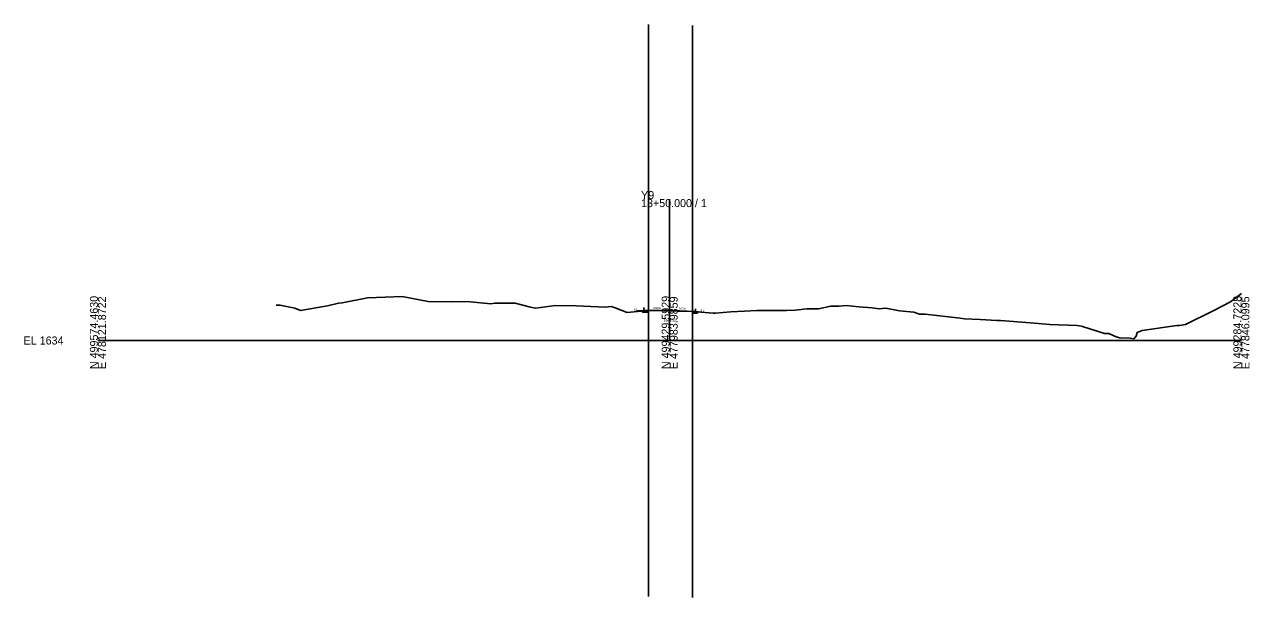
# Model space of a CAD drawing. Extents: x -26 to 403, y -99 to 4540.
# Drawn here: x -25.7 to 402.8, y 3410.1 to 3610.5 of the extents above; entities that cross this region are included whole.
import ezdxf

# ---------------------------------------------------------------- set-up
doc = ezdxf.new("R2010")
doc.units = 0
for name, color, linetype in [('Exist Cross Section Cell', 7, 'Continuous'), ('Exist XS Center Line Elevation Label', 7, 'Continuous'), ('Exist XS Ground Line', 7, 'Continuous'), ('Prop XS Ditch Slope Text', 7, 'Continuous'), ('Prop XS Dump Level', 7, 'Continuous'), ('Prop XS Earthwork Shape', 7, 'Continuous'), ('Prop XS EOT Tick Mark', 7, 'Continuous'), ('Prop XS Finish Grade', 7, 'Continuous'), ('Prop XS Finish Grade Earthwork', 7, 'Continuous'), ('Prop XS Finish Grade Pavement', 7, 'Continuous'), ('Prop XS Pvmt Edge Slope', 7, 'Continuous'), ('Prop XS SE Text', 7, 'Continuous'), ('Prop XS Shoulder Borrow Shape', 7, 'Continuous'), ('Prop XS Subgrade Earthwork', 7, 'Continuous'), ('Scratch_Level_1', 7, 'Continuous'), ('Scratch_Level_6', 7, 'Continuous')]:
    doc.layers.add(name, color=color, linetype=linetype)

msp = doc.modelspace()

# ---------------------------------------------------------------- linework, layer by layer
at = {"layer": 'Exist Cross Section Cell'}
for p, q in [((200, 3500), (200, 3549.45)), ((0, 3500), (200, 3500)), ((200, 3500), (400, 3500))]:
    msp.add_line(p, q, dxfattribs=at)
at = {"layer": 'Exist XS Ground Line'}
msp.add_lwpolyline([(62.34, 3512.39), (63.63, 3512.39), (68.89, 3511.28), (70.83, 3510.51), (80.28, 3512.18), (84.11, 3513.04), (85.43, 3513.17), (94.26, 3514.89), (100.44, 3515.1), (106.38, 3515.33), (115.5, 3513.69), (123.68, 3513.53), (129.04, 3513.68), (137.49, 3512.87), (138.86, 3513.04), (140.31, 3513.08), (145.94, 3513.09), (151.3, 3511.69), (153.01, 3511.35), (154.82, 3511.53), (160.09, 3512.24), (167.35, 3512.12), (177.58, 3511.6), (178.52, 3511.79), (179.63, 3511.86), (180.88, 3511.42), (185.19, 3509.78), (189.96, 3510.27), (192.61, 3510.5), (197.61, 3510.5), (200, 3510.52), (201.26, 3510.45), (208.03, 3510.14), (215.24, 3509.57), (216.01, 3509.51), (221.43, 3510.01), (226.15, 3510.3), (230.45, 3510.49), (241.03, 3510.49), (243.9, 3510.55), (247.95, 3511.06), (252.06, 3511.03), (256.37, 3512), (259.13, 3512.05), (261.76, 3512.2), (266.21, 3511.75), (270.88, 3511.44), (273.28, 3511.05), (275.57, 3511.32), (280.36, 3510.43), (285.38, 3509.88), (287.43, 3509.22), (289.38, 3509.26), (301.58, 3507.83), (303.19, 3507.52), (308.65, 3507.29), (314.4, 3507.05), (315.73, 3507.04), (318.77, 3506.79), (327.57, 3506.12), (332.99, 3505.59), (342.58, 3505.19), (343.9, 3504.98), (344.37, 3504.91), (352.12, 3502.45), (353.64, 3502.44), (356.16, 3501.3), (357.44, 3500.98), (361.05, 3500.82), (362.43, 3500.64), (363.15, 3501.56), (363.54, 3502.83), (365.3, 3503.44), (377.44, 3505.21), (378.36, 3505.28), (380.44, 3505.6), (390.38, 3510.54), (396.14, 3513.53), (400, 3516.48)], dxfattribs=at)
at = {"layer": 'Prop XS Dump Level'}
for p, q in [((191, 3510.49), (200, 3510.52)), ((200, 3510.52), (209, 3510.09))]:
    msp.add_line(p, q, dxfattribs=at)
at = {"layer": 'Prop XS Earthwork Shape'}
for p, q in [((189, 3510.37), (188.19, 3510.09)), ((188.19, 3510.09), (189.96, 3510.27)), ((189.98, 3510.43), (189, 3510.37)), ((189.96, 3510.27), (190.13, 3510.28)), ((190.13, 3510.28), (189.98, 3510.43)), ((190.85, 3510.34), (190.13, 3510.28)), ((190.13, 3510.28), (190.46, 3509.95)), ((190.85, 3510.34), (190.46, 3509.95)), ((190.46, 3509.95), (190.85, 3510.34)), ((190.46, 3509.95), (191, 3509.95)), ((192.6, 3510.5), (190.85, 3510.34)), ((191, 3509.95), (192.61, 3509.96)), ((192.61, 3510.5), (192.6, 3510.5)), ((192.61, 3510.5), (192.61, 3510.5)), ((192.61, 3509.96), (192.61, 3510.5)), ((209.04, 3510.06), (208.03, 3510.14)), ((208.03, 3510.14), (208.03, 3509.6)), ((210.02, 3509.98), (209.04, 3510.06)), ((209.57, 3509.53), (210.02, 3509.98)), ((210.05, 3510.01), (210.02, 3509.98)), ((210.02, 3509.98), (211.19, 3509.89)), ((211, 3509.93), (210.05, 3510.01)), ((211.19, 3509.89), (211, 3509.93)), ((208.03, 3509.6), (209, 3509.55)), ((209, 3509.55), (209.57, 3509.53))]:
    msp.add_line(p, q, dxfattribs=at)
at = {"layer": 'Prop XS EOT Tick Mark'}
for p, q in [((191, 3510.49), (191, 3511.49)), ((209, 3510.09), (209, 3511.09))]:
    msp.add_line(p, q, dxfattribs=at)
at = {"layer": 'Prop XS Finish Grade'}
for p, q in [((191, 3510.49), (189.98, 3510.43)), ((209, 3510.09), (210.05, 3510.01))]:
    msp.add_line(p, q, dxfattribs=at)
at = {"layer": 'Prop XS Finish Grade Earthwork'}
for p, q in [((189, 3510.37), (188.19, 3510.09)), ((189.98, 3510.43), (189, 3510.37)), ((210.05, 3510.01), (211, 3509.93)), ((211, 3509.93), (211.19, 3509.89))]:
    msp.add_line(p, q, dxfattribs=at)
at = {"layer": 'Prop XS Finish Grade Pavement'}
for p, q in [((191, 3510.49), (200, 3510.52)), ((200, 3510.52), (209, 3510.09))]:
    msp.add_line(p, q, dxfattribs=at)
at = {"layer": 'Prop XS Pvmt Edge Slope'}
for p, q in [((191, 3510.49), (190.46, 3509.95)), ((209, 3510.09), (209.57, 3509.53))]:
    msp.add_line(p, q, dxfattribs=at)
at = {"layer": 'Prop XS Shoulder Borrow Shape'}
for points in [[(191, 3510.49), (189.98, 3510.43), (190.46, 3509.95)], [(209.57, 3509.53), (210.05, 3510.01), (209, 3510.09)]]:
    msp.add_lwpolyline(points, close=True, dxfattribs=at)
at = {"layer": 'Prop XS Subgrade Earthwork'}
for p, q in [((190.46, 3509.95), (189.98, 3510.43)), ((191, 3509.95), (190.46, 3509.95)), ((192.61, 3509.96), (191, 3509.95)), ((192.61, 3509.96), (192.63, 3510.5)), ((208.03, 3509.6), (208.03, 3510.14)), ((209.57, 3509.53), (210.05, 3510.01)), ((209, 3509.55), (208.03, 3509.6)), ((209, 3509.55), (209.57, 3509.53))]:
    msp.add_line(p, q, dxfattribs=at)
at = {"layer": 'Scratch_Level_1'}
for p, q in [((192.61, 3610.5), (192.61, 3410.5)), ((208.03, 3610.14), (208.03, 3410.14))]:
    msp.add_line(p, q, dxfattribs=at)
at = {"layer": 'Scratch_Level_6'}
msp.add_line((192.63, 3510.5), (208.03, 3510.14), dxfattribs=at)

# ---------------------------------------------------------------- texts
at = {"layer": 'Exist Cross Section Cell'}
for s, p in [('Y9', (190, 3549.45)), ('13+50.000 / 1', (190, 3546.65)), ('EL 1634', (-26, 3498.6))]:
    msp.add_text(s, height=2.8, dxfattribs=at).set_placement(p)
for s, p in [('N 499574.4630', (0, 3490)), ('E 478121.8722', (2.8, 3490)), ('N 499429.5929', (200, 3490)), ('E 477983.9859', (202.8, 3490)), ('N 499284.7228', (400, 3490)), ('E 477846.0995', (402.8, 3490))]:
    msp.add_text(s, height=2.8, rotation=90, dxfattribs=at).set_placement(p)
at = {"layer": 'Exist XS Center Line Elevation Label'}
msp.add_text('1644.52', height=0.9, dxfattribs=at).set_placement((197.88, 3506.62))
at = {"layer": 'Prop XS Ditch Slope Text'}
for rotation, p in [(14.0362, (187.46, 3510.29)), (345.9638, (210.73, 3510.34))]:
    msp.add_text('3:1', height=0.75, rotation=rotation, dxfattribs=at).set_placement(p)
at = {"layer": 'Prop XS Dump Level'}
msp.add_text('Case1', height=0.04, dxfattribs=at).set_placement((189, 3510.33))
at = {"layer": 'Prop XS SE Text'}
for s, rotation, p in [('0.003', 0.149, (194.2, 3511)), ('0.047', 357.3091, (203.19, 3510.87))]:
    msp.add_text(s, height=0.75, rotation=rotation, dxfattribs=at).set_placement(p)

doc.saveas('drawing.dxf')
